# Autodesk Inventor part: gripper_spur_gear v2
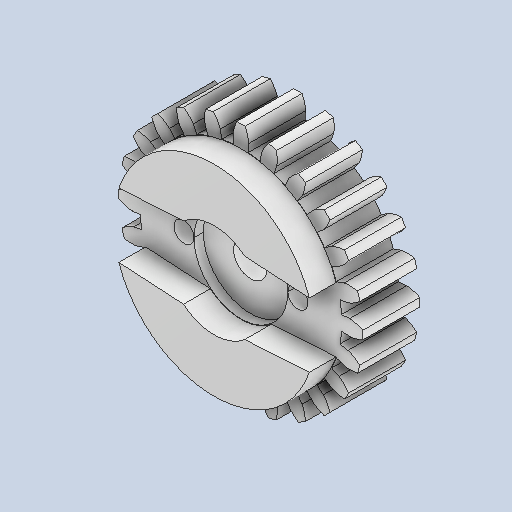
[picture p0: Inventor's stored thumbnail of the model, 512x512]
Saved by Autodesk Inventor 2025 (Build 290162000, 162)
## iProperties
Created: 2025-06
Part Number: gripper_spur_gear v2
Material: Plastica ABS
Document SubType Name: Modeling
Designer: Ryzen5700u
Density: 1.06 g/cm^3
Appearance: Default
Author: Ryzen5700u
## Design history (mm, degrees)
feature "Solido1"
node "Solido2"
